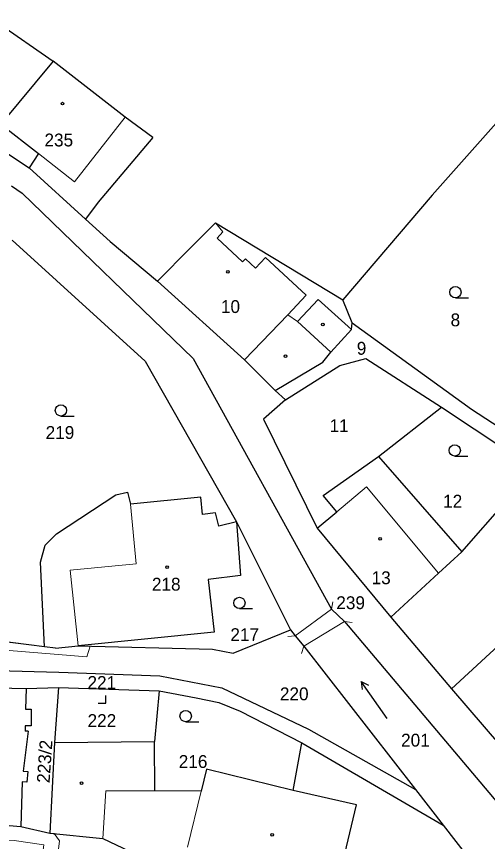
# Model space of a CAD drawing. Extents: x -727701 to -724405, y -960481 to -957284.
# Drawn here: x -726869.9 to -726807.6, y -958085.7 to -957976.6 of the extents above; entities that cross this region are included whole.
import ezdxf
from ezdxf.enums import TextEntityAlignment as Align

# ---------------------------------------------------------------- set-up
doc = ezdxf.new("R2010")
doc.units = 0
doc.header["$LTSCALE"] = 0.68
for name, color, linetype, lineweight in [('1', 7, 'Continuous', 25), ('13', 7, 'Continuous', 13), ('3', 7, 'Continuous', 25), ('4', 7, 'Continuous', 13), ('5', 7, 'Continuous', 25)]:
    doc.layers.add(name, color=color, linetype=linetype, lineweight=lineweight)
doc.layers.add('2', color=7, linetype='Continuous')

msp = doc.modelspace()

# ---------------------------------------------------------------- linework, layer by layer
at = {"layer": '1'}
for p, q in [((-726873.6, -957976.62), (-726865.05, -957982.52)), ((-726797.61, -957980.7), (-726814.9, -958000.25)), ((-726865.05, -957982.52), (-726871.99, -957990.85)), ((-726855.51, -957989.91), (-726865.05, -957982.52)), ((-726879.91, -957988.93), (-726868.24, -957996.62)), ((-726851.87, -957992.63), (-726855.51, -957989.91)), ((-726871.99, -957990.85), (-726867, -957994.75)), ((-726851.87, -957992.63), (-726859.08, -958001.18)), ((-726867, -957994.75), (-726868.24, -957996.62)), ((-726868.24, -957996.62), (-726860.78, -958003.42)), ((-726870.57, -957999.01), (-726869.17, -957999.98)), ((-726869.17, -957999.98), (-726846.51, -958021.81)), ((-726814.9, -958000.25), (-726826.75, -958014.06)), ((-726859.08, -958001.18), (-726860.78, -958003.42)), ((-726860.78, -958003.42), (-726857.49, -958006.35)), ((-726846.9, -958007.2), (-726843.57, -958003.91)), ((-726843.57, -958003.91), (-726826.75, -958014.06)), ((-726870.48, -958006.17), (-726852.89, -958022.19)), ((-726857.49, -958006.35), (-726851.24, -958011.6)), ((-726851.24, -958011.6), (-726846.9, -958007.2)), ((-726851.24, -958011.6), (-726839.75, -958022)), ((-726825.5, -958017.11), (-726826.75, -958014.06)), ((-726825.6, -958017.98), (-726825.5, -958017.11)), ((-726825.5, -958017.11), (-726809.73, -958028.54)), ((-726828.3, -958021), (-726825.6, -958017.98)), ((-726829.38, -958022.32), (-726828.3, -958021)), ((-726852.89, -958022.19), (-726840.78, -958043.4)), ((-726846.51, -958021.81), (-726828.22, -958054.98)), ((-726839.75, -958022), (-726835.68, -958026.08)), ((-726827.11, -958022.77), (-726823.71, -958021.85)), ((-726823.71, -958021.85), (-726813.67, -958028.25)), ((-726835.68, -958026.08), (-726829.38, -958022.32)), ((-726834.3, -958027.3), (-726827.11, -958022.77)), ((-726835.68, -958026.08), (-726834.3, -958027.3)), ((-726834.3, -958027.3), (-726837.24, -958029.84)), ((-726822, -958034.8), (-726813.67, -958028.25)), ((-726813.67, -958028.25), (-726801.41, -958036.44)), ((-726809.73, -958028.54), (-726800.87, -958034.27)), ((-726837.24, -958029.84), (-726830.13, -958044.27)), ((-726829.32, -958039.94), (-726822, -958034.8)), ((-726822, -958034.8), (-726811, -958047.4)), ((-726811, -958047.4), (-726801.41, -958036.44)), ((-726856.74, -958039.84), (-726855.21, -958039.5)), ((-726855.21, -958039.5), (-726854.84, -958041.09)), ((-726864.6, -958045.01), (-726856.74, -958039.84)), ((-726845.52, -958040.16), (-726854.84, -958041.09)), ((-726845.29, -958042.45), (-726845.52, -958040.16)), ((-726827.52, -958042.09), (-726829.32, -958039.94)), ((-726843.57, -958042.24), (-726845.29, -958042.45)), ((-726843.15, -958043.98), (-726843.57, -958042.24)), ((-726830.13, -958044.27), (-726827.52, -958042.09)), ((-726840.78, -958043.4), (-726843.15, -958043.98)), ((-726840.78, -958043.4), (-726833.64, -958057.72)), ((-726840.78, -958043.4), (-726840.25, -958050.5)), ((-726866.1, -958046.49), (-726864.6, -958045.01)), ((-726830.13, -958044.27), (-726820.4, -958056.02)), ((-726866.71, -958048.75), (-726866.1, -958046.49)), ((-726814.07, -958050.21), (-726811, -958047.4)), ((-726866.2, -958059.93), (-726866.71, -958048.75)), ((-726840.25, -958050.5), (-726844.55, -958051.05)), ((-726820.4, -958056.02), (-726814.07, -958050.21)), ((-726844.55, -958051.05), (-726843.74, -958058.02)), ((-726828.22, -958054.98), (-726826.51, -958056.58)), ((-726812.34, -958065.48), (-726799.94, -958054)), ((-726820.4, -958056.02), (-726812.34, -958065.48)), ((-726826.51, -958056.58), (-726797.94, -958090.46)), ((-726866.2, -958059.93), (-726883.16, -958057.83)), ((-726843.74, -958058.02), (-726861.74, -958059.81)), ((-726841.25, -958060.8), (-726833.64, -958057.72)), ((-726833.64, -958057.72), (-726833.02, -958058.48)), ((-726833.02, -958058.48), (-726831.88, -958059.88)), ((-726864.73, -958060.11), (-726866.2, -958059.93)), ((-726864.73, -958060.11), (-726861.74, -958059.81)), ((-726861.74, -958059.81), (-726843.97, -958060.26)), ((-726843.97, -958060.26), (-726841.25, -958060.8)), ((-726831.88, -958059.88), (-726817.14, -958078.81)), ((-726889.82, -958062.58), (-726864.31, -958063.31)), ((-726864.31, -958063.31), (-726850.95, -958063.77)), ((-726850.95, -958063.77), (-726842.73, -958065.36)), ((-726874.35, -958065.33), (-726868.64, -958065.45)), ((-726868.64, -958065.45), (-726868.7, -958068.18)), ((-726868.64, -958065.45), (-726864.36, -958065.31)), ((-726864.36, -958065.31), (-726864.88, -958072.6)), ((-726864.36, -958065.31), (-726851.02, -958065.77)), ((-726851.02, -958065.77), (-726851.66, -958072.46)), ((-726851.02, -958065.77), (-726846.13, -958066.7)), ((-726842.73, -958065.36), (-726831.28, -958070.82)), ((-726812.34, -958065.48), (-726805.89, -958073.05)), ((-726846.13, -958066.7), (-726843.14, -958067.32)), ((-726843.14, -958067.32), (-726840.31, -958068.44)), ((-726868.7, -958068.18), (-726867.94, -958068.19)), ((-726867.94, -958068.19), (-726867.98, -958070.4)), ((-726840.31, -958068.44), (-726832.15, -958072.62)), ((-726868.35, -958071.09), (-726869.03, -958076.39)), ((-726868.74, -958070.39), (-726868.77, -958071.08)), ((-726868.35, -958071.09), (-726868.77, -958071.08)), ((-726867.98, -958070.4), (-726868.74, -958070.39)), ((-726831.28, -958070.82), (-726817.14, -958078.81)), ((-726864.88, -958072.6), (-726851.66, -958072.46)), ((-726851.61, -958079), (-726851.66, -958072.46)), ((-726864.88, -958072.6), (-726865.48, -958084.56)), ((-726833.31, -958078.94), (-726832.15, -958072.62)), ((-726832.15, -958072.62), (-726813.46, -958083.54)), ((-726869.03, -958076.39), (-726868.41, -958076.44)), ((-726868.41, -958076.44), (-726868.51, -958077.82)), ((-726844.78, -958076.14), (-726845.48, -958079.04)), ((-726833.31, -958078.94), (-726844.78, -958076.14)), ((-726869.13, -958077.78), (-726869.32, -958083.69)), ((-726868.51, -958077.82), (-726869.13, -958077.78)), ((-726845.48, -958079.04), (-726851.61, -958079)), ((-726824.94, -958080.83), (-726833.31, -958078.94)), ((-726817.14, -958078.81), (-726813.46, -958083.54)), ((-726828.85, -958097.47), (-726824.94, -958080.83)), ((-726877.28, -958083.06), (-726869.32, -958083.69)), ((-726869.32, -958083.69), (-726865.48, -958084.56)), ((-726813.46, -958083.54), (-726806.79, -958092.11)), ((-726865.48, -958084.56), (-726858.5, -958085.29)), ((-726858.5, -958085.29), (-726842.95, -958092.6))]:
    msp.add_line(p, q, dxfattribs=at)
at = {"layer": '13'}
msp.add_lwpolyline([(-726881.7, -958059.57), (-726860.58, -958061.26), (-726860.16, -958059.85), (-726861.74, -958059.81), (-726864.73, -958060.11), (-726883.16, -958057.83)], dxfattribs=at)
msp.add_lwpolyline([(-726881.32, -958083.06), (-726889.47, -958083.69), (-726906.79, -958087.87), (-726906.11, -958090.11), (-726895.99, -958086.64), (-726888.66, -958085.1), (-726881.81, -958084.9), (-726870.2, -958085.53), (-726866.28, -958086.13), (-726866.49, -958087.81), (-726865.02, -958087.99), (-726864.47, -958087.79), (-726864.2, -958085.58), (-726864.93, -958084.62), (-726865.48, -958084.56), (-726869.32, -958083.69), (-726877.28, -958083.06), (-726878.58, -958082.9)], close=True, dxfattribs=at)
at = {"layer": '3'}
for p, q in [((-726811.843, -958013.81), (-726810.093, -958013.81)), ((-726864.023, -958029.44), (-726862.273, -958029.44)), ((-726811.933, -958034.73), (-726810.183, -958034.73)), ((-726840.423, -958054.89), (-726838.673, -958054.89)), ((-726824.314, -958064.514), (-726823.342, -958065.026)), ((-726847.523, -958069.85), (-726845.773, -958069.85))]:
    msp.add_line(p, q, dxfattribs=at)
for points in [[(-726820.872, -958069.428), (-726824.314, -958064.514), (-726824.164, -958065.602)], [(-726859.101, -958067.38), (-726858.1, -958067.38), (-726858.1, -958066.38)]]:
    msp.add_lwpolyline(points, dxfattribs=at)
for centre in [(-726811.8429, -958013.0598), (-726864.0229, -958028.6898), (-726811.9329, -958033.9798), (-726840.4229, -958054.1398), (-726847.5229, -958069.0998)]:
    msp.add_circle(centre, 0.75, dxfattribs=at)
at = {"layer": '4'}
for p, q in [((-726862.24, -957998.46), (-726855.51, -957989.91)), ((-726867, -957994.75), (-726862.24, -957998.46)), ((-726843.57, -958003.91), (-726842.61, -958005.1)), ((-726842.61, -958005.1), (-726843.37, -958005.92)), ((-726843.37, -958005.92), (-726840.01, -958009.04)), ((-726840.01, -958009.04), (-726839.63, -958008.64)), ((-726839.63, -958008.64), (-726838.29, -958009.9)), ((-726838.29, -958009.9), (-726836.97, -958008.48)), ((-726836.97, -958008.48), (-726831.6, -958013.45)), ((-726831.6, -958013.45), (-726834, -958016.05)), ((-726832.75, -958016.95), (-726830, -958014.05)), ((-726830, -958014.05), (-726825.6, -958017.98)), ((-726834, -958016.05), (-726839.75, -958022)), ((-726834, -958016.05), (-726832.75, -958016.95)), ((-726832.75, -958016.95), (-726828.3, -958021)), ((-726827.52, -958042.09), (-726823.61, -958038.81)), ((-726823.61, -958038.81), (-726814.07, -958050.21)), ((-726854.84, -958041.09), (-726854.05, -958048.97)), ((-726854.05, -958048.97), (-726862.8, -958049.83)), ((-726861.74, -958059.81), (-726862.8, -958049.83)), ((-726833.02, -958058.48), (-726828.22, -958054.98)), ((-726828.046, -958053.995), (-726828.219, -958054.98)), ((-726826.51, -958056.58), (-726831.88, -958059.88)), ((-726825.519, -958056.72), (-726826.51, -958056.581)), ((-726834.017, -958058.567), (-726833.021, -958058.479)), ((-726832.223, -958060.82), (-726831.881, -958059.88)), ((-726858.07, -958078.97), (-726858.5, -958085.29)), ((-726858.07, -958078.97), (-726851.61, -958079)), ((-726847.27, -958086.45), (-726845.48, -958079.04))]:
    msp.add_line(p, q, dxfattribs=at)
at = {"layer": '5'}
for centre in [(-726863.8268, -957988.1392), (-726841.9268, -958010.3692), (-726829.3868, -958017.3392), (-726834.3168, -958021.5292), (-726821.8168, -958045.6692), (-726849.9868, -958049.4192), (-726861.2868, -958077.9792), (-726836.0768, -958084.8092)]:
    msp.add_circle(centre, 0.175, dxfattribs=at)

# ---------------------------------------------------------------- texts
at = {"layer": '2'}
for s, p in [('235', (-726866.2, -957993.795)), ('10', (-726842.86, -958015.815)), ('8', (-726812.48, -958017.575)), ('9', (-726824.89, -958021.335)), ('12', (-726813.47, -958041.545)), ('13', (-726822.93, -958051.665)), ('239', (-726827.6, -958054.965)), ('217', (-726841.61, -958059.185)), ('221', (-726860.51, -958065.515)), ('220', (-726835.06, -958067.015)), ('222', (-726860.5, -958070.545)), ('201', (-726819.03, -958073.135)), ('216', (-726848.44, -958075.955))]:
    msp.add_text(s, height=1.7, dxfattribs=at).set_placement(p)
for s, p in [('11', (-726827.229, -958031.565)), ('219', (-726864.149, -958032.465)), ('218', (-726850.089, -958052.515))]:
    msp.add_text(s, height=1.7, dxfattribs=at).set_placement(p, align=Align.CENTER)
msp.add_text('223/2', height=1.7, rotation=86, dxfattribs=at).set_placement((-726865.526, -958077.999))

doc.saveas('drawing.dxf')
